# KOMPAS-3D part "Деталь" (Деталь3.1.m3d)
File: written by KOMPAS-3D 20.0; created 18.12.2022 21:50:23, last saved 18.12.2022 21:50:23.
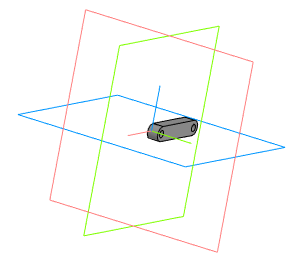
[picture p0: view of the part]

Document properties: Полное имя файла: C:\Users\Семья\Desktop\ДЕТАЛИ ДЛЯ СБОРЩИКА БОРЩЕВИКА\Деталь3.1.m3d

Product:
- Part/product: Деталь
    Масса: 0.00165643

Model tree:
1. Эскиз:1
2. Элемент выдавливания:1
     Расстояние 1 = 3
